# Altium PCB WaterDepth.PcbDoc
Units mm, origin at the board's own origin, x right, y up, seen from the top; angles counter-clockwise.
Board outline 26.42 x 32.13 mm, 2 copper layers (Top Layer, Bottom Layer); 43 components, 29 nets, 142 pads, 35 vias.
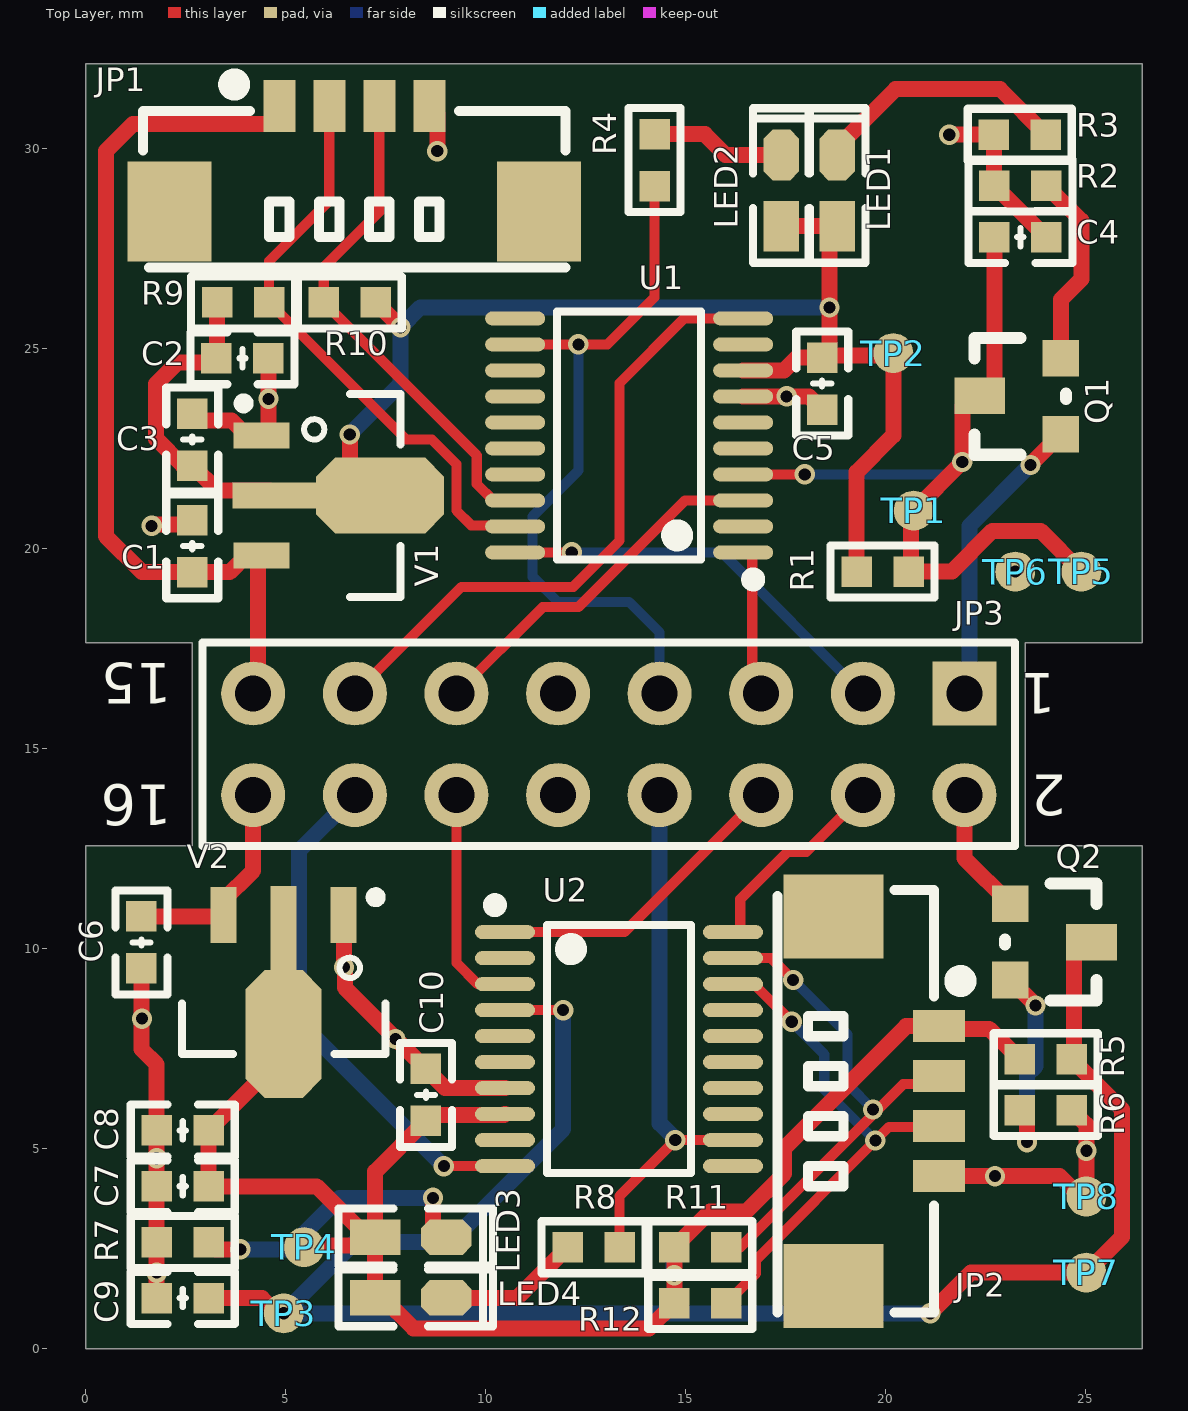
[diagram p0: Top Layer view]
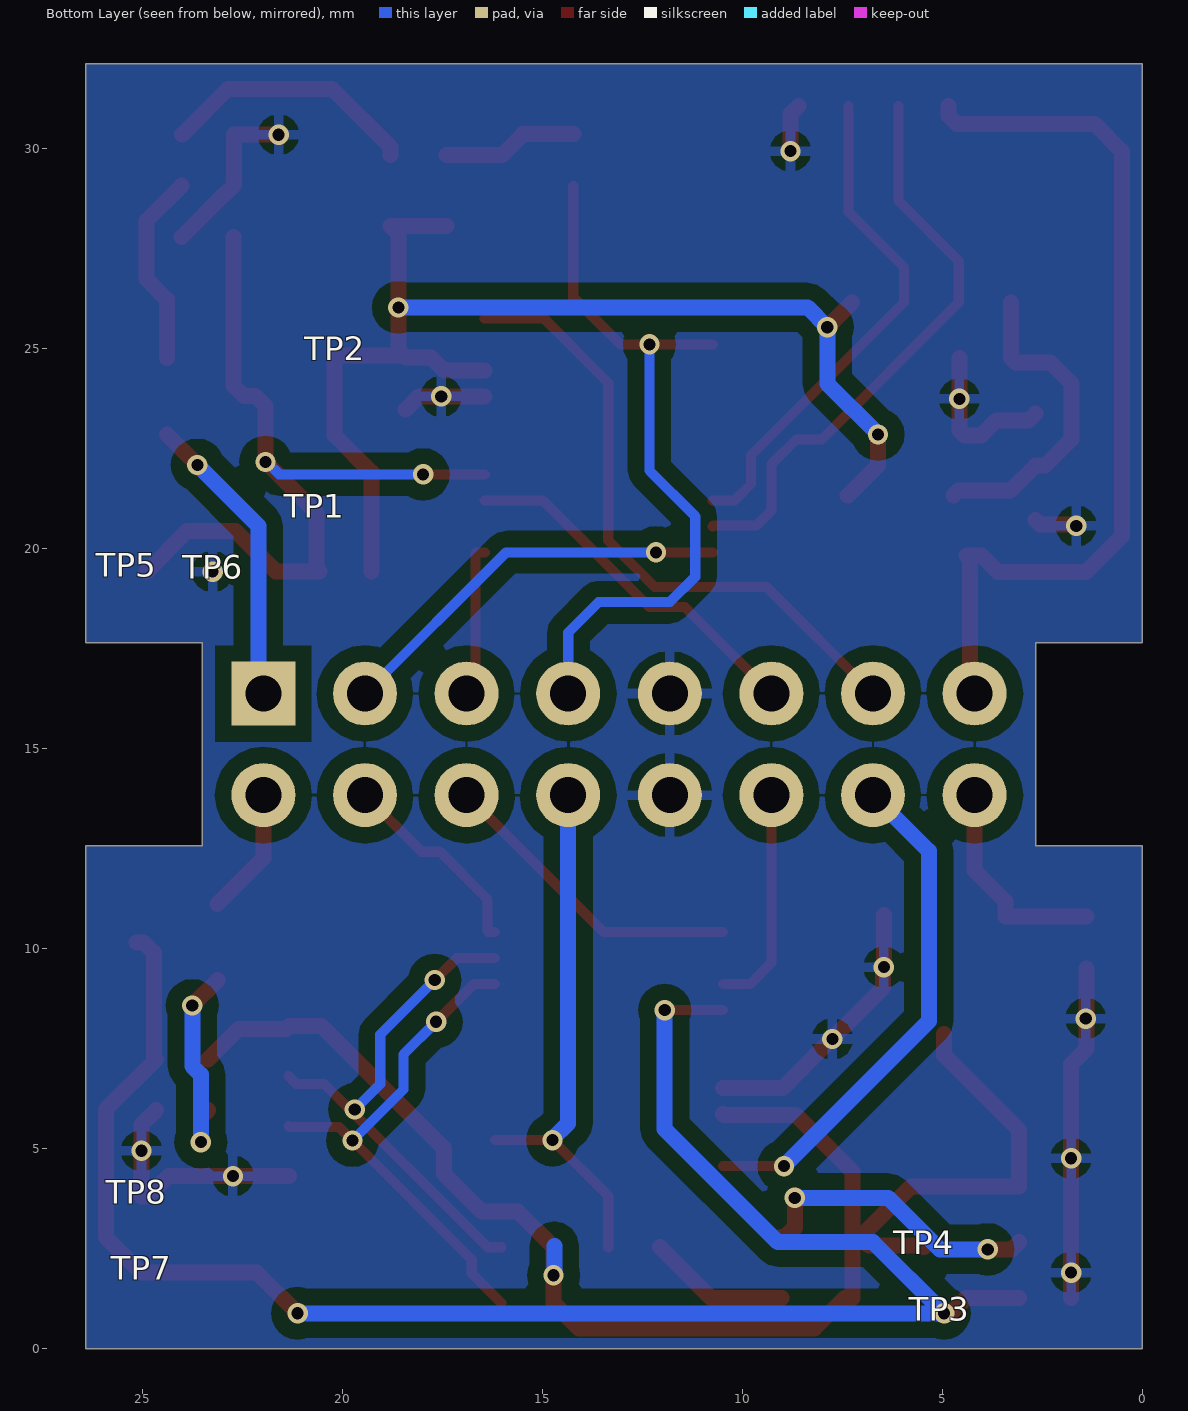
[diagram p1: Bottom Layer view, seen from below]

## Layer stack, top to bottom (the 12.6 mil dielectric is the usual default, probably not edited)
Top Solder: solder mask 0.0102, Solder Resist, Dk 3.5
Top Layer: signal copper 0.0356
Dielectric 1: dielectric 0.32, FR-4, Dk 4.8
Bottom Layer: signal copper 0.0356
Bottom Solder: solder mask 0.0102, Solder Resist, Dk 3.5

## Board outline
0,0 26.416,0 26.416,12.573 23.495,12.573 23.495,17.653 26.416,17.653 26.416,32.131 0,32.131 0,17.653 2.667,17.653 2.667,12.573 0,12.573

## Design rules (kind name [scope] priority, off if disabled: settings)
Clearance [All] p1: gap=0 ignorepadtopadclearanceinfootprint=FALSE
PolygonConnect [All] p1: connectstyle=Relief reliefconductorwidth=0.254 reliefentries=4 polygonreliefangle="90 Angle" airgapwidth=0.254
RoutingVias [All] p1: holewidth=0.711 width=1.27 viastyle="Through Hole" minholewidth=0.711 minwidth=1.27 maxholewidth=0.711 maxwidth=1.27
SilkToSilkClearance [All] p1: silktosilkclearance=0
SolderMaskExpansion [All] p1: expansion=0.102
Width [All] p1: maxlimit=1.5 minlimit=0.254 preferedwidth=0.4
29 further rules are at their usual default settings.

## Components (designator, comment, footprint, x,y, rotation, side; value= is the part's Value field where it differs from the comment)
C1 "104" "C 0603_L" 2.667,20.066 r270 top
C2 "104" "C 0603_L" 3.922,24.765 r180 top
C3 "104" "C 0603_L" 2.667,22.733 r270 top
C4 "104" "C 0603_L" 23.368,27.793 r180 top
C5 "104" "C 0603_L" 18.415,24.13 r90 top
C6 "104" "C 0603_L" 1.397,10.16 r90 top
C7 "104" "C 0603_L" 2.428,4.064 r0 top
C8 "104" "C 0603_L" 2.428,5.461 r0 top
C9 "104" "C 0603_L" 2.428,1.27 r0 top
C10 "104" "C 0603_L" 8.509,6.35 r270 top
JP1 "HDR-1X4" "MX 1.25-LS-4P" 6.731,28.814 r0 top
JP2 "HDR-1X4" "MX 1.25-LS-4P" 19.075,6.179 r270 top
JP3 "Header 8X2" HDR2.54-LI-2x8P 13.081,15.113 r180 top
LED1 "红色" "LED 0603W" 18.796,28.956 r90 top
LED2 "红色" "LED 0603W" 17.399,28.956 r90 top
LED3 "红色" "LED 0603W" 8.128,2.787 r0 top
LED4 "红色" "LED 0603W" 8.128,1.27 r0 top
Q1 "NPN" SOT-23 23.495,23.749 r90 top
Q2 "NPN" SOT-23 24.003,10.236 r270 top
R1 "33K" "R 0603_L" 19.924,19.431 r180 top
R2 "3.3K" "R 0603_L" 23.368,29.083 r0 top
R3 "3.3K" "R 0603_L" 23.353,30.353 r0 top
R4 "3.3K" "R 0603_L" 14.224,29.718 r90 top
R5 "33K" "R 0603_L" 24.003,7.239 r180 top
R6 "3.3K" "R 0603_L" 24.003,5.969 r180 top
R7 "3.3K" "R 0603_L" 2.428,2.667 r0 top
R8 "3.3K" "R 0603_L" 12.7,2.54 r180 top
R9 "4.7K" "R 0603_L" 3.937,26.162 r180 top
R10 "4.7K" "R 0603_L" 6.604,26.162 r0 top
R11 "4.7K" "R 0603_L" 15.367,2.54 r180 top
R12 "4.7K" "R 0603_L" 15.367,1.143 r180 top
TP1 "TEST" "TEST 1" 20.701,20.955 r180 top
TP2 "TEST" "TEST 1" 20.193,24.892 r270 top
TP3 "TEST" "TEST 1" 4.953,0.889 r90 top
TP4 "TEST" "TEST 1" 5.461,2.54 r90 top
TP5 "TEST" "TEST 1" 24.892,19.431 r90 top
TP6 "TEST" "TEST 1" 23.241,19.431 r90 top
TP7 "TEST" "TEST 1" 25.019,1.905 r90 top
TP8 "TEST" "TEST 1" 25.019,3.81 r90 top
U1 "STM8L101F3P6" TSSOP-20 13.589,22.836 r90 top
U2 "STM8L101F3P6" TSSOP-20 13.335,7.493 r270 top
V1 "AMS1117-3V3" SOT89_N 6.35,21.336 r270 top
V2 "AMS1117-3V3" SOT89_N 4.953,8.89 r180 top

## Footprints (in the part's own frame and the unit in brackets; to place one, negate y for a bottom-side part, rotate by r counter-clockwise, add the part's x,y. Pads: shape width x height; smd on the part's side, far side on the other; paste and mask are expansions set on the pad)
"C 0603_L" [mil] "无极性贴片电容"
  rect 30x30 smd: 1(-25.59,0) 2(25.59,0)
  silkscreen extent -51,-26 51,26, body extent -31,-16 31,16, height 32
HDR2.54-LI-2x8P [mm] "双排排针，8x2脚"
  rect 1.6x1.6 hole 0.9: 1(-8.89,-1.27)
  round 1.6 hole 0.9: 2(-8.89,1.27) 3(-6.35,-1.27) 4(-6.35,1.27) 5(-3.81,-1.27) 6(-3.81,1.27) 7(-1.27,-1.27) 8(-1.27,1.27) 9(1.27,-1.27) 10(1.27,1.27) 11(3.81,-1.27) 12(3.81,1.27) 13(6.35,-1.27) 14(6.35,1.27) 15(8.89,-1.27) 16(8.89,1.27)
  silkscreen extent -10.16,-2.54 10.16,2.54, body extent -10.16,-2.54 10.16,2.54, height 8.5
"LED 0603W" [mil] "白色0603LED"
  rect 50x35 smd: 1(-35,0.26)
  oct 50x35 smd: 2(35,0.26)
  silkscreen extent -71,-28 81,28, body extent -31,-16 32,16, height 18
"MX 1.25-LS-4P" [mm] "长：9.75m，宽：3.7mm，高：4.7mm"
  rect 2.1x2.5 smd: 0(-4.632,-0.381) 0(4.604,-0.381)
  rect 0.8x1.3 smd: 1(-1.889,2.261) 2(-0.639,2.261) 3(0.611,2.261) 4(1.861,2.261)
  silkscreen extent -5.29,-1.78 5.27,2.99, body extent -5.07,-1.6 5.07,2.5, height 4.7
"R 0603_L" [mil] "1/10W贴片电阻"
  rect 30x30 smd: 1(-25.59,0) 2(25.59,0)
  silkscreen extent -51,-26 51,26, body extent -31,-16 32,16, height 16
SOT89_N [mm] "4.6x4.3x1.6mm(长宽高)"
  rect 0.65x1.4 smd: 1(-1.5,-1.952) 3(1.5,-1.952)
  oct 1.9x3.2 smd: 2(0,1.016)
  rect 0.65x2.1 smd: 2(0,-1.626)
  silkscreen extent -2.54,-2.52 2.54,1.52, body extent -2.3,-2.4 2.3,1.9, height 1.6
SOT-23 [mil]
  rect 36x36 smd: B(-35,-35) E(40,-35)
  rect 36x50 smd: C(3,45)
  silkscreen extent -55,-40 60,50, body extent -54,-48 60,62, height 47
"TEST 1" [mm] "测试点1mm"
  round 1 smd paste-1: 1(0,0)
TSSOP-20 [mm]
  oval 0.35x1.5 smd: 1(-2.925,-2.85) 2(-2.275,-2.85) 3(-1.625,-2.85) 4(-0.975,-2.85) 5(-0.325,-2.85) 6(0.325,-2.85) 7(0.975,-2.85) 8(1.625,-2.85) 9(2.275,-2.85) 10(2.925,-2.85) 11(2.925,2.85) 12(2.275,2.85) 13(1.625,2.85) 14(0.975,2.85) 15(0.325,2.85) 16(-0.325,2.85) 17(-0.975,2.85) 18(-1.625,2.85) 19(-2.275,2.85) 20(-2.925,2.85)
  silkscreen extent -3.75,-3.25 3.1,1.8

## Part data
C1 C2 C3 C4 C5 C6 C7 C8 C9 C10: library part C, "无极性贴片电容"
JP1 JP2: library part "Header 4", "4P接插件"
JP3: "8*2P接插件"
LED1 LED2 LED3 LED4: library part LED-SMD, "贴片LED"
Q1 Q2: "NPN三极管"
R1 R2 R3 R4 R5 R6 R7 R8 R9 R10 R11 R12: library part R, "贴片电阻"
TP1 TP2 TP3 TP4 TP5 TP6 TP7 TP8: "测试点"
U1 U2: "MCU", Package=TSSOP-20, SuppliersPartNumber=C30044
V1 V2: library part AMS1117, "三端稳压芯片"

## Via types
v1: diameter 0.508, hole 0.305, Top Layer to Bottom Layer, tented both sides, 35 vias

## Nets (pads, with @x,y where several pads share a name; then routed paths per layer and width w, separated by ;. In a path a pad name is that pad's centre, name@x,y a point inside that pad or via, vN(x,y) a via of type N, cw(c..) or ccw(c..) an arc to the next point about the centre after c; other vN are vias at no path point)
3V3: C2.2 C3.2 C5.2 LED1.1 LED2.1 R1.2 R9.2 R10.2 TP2.1 U1.8 V1.2 | length 39.4
  Top Layer w0.4: R9.2 3.28,26.155 3.28,24.773 C2.2 3.16,24.653 2.291,24.653 1.763,24.125 1.763,22.748 2.428,22.083 C3.2 3.289,21.461 4.599,21.461 V1.2@4.724,21.336 ; v1(6.604,22.86) 6.604,22.086 7.354,21.336 V1.2@7.366,21.336 ; R10.2 v1(7.874,25.542) ; U1.8 17.461,24.461 17.78,24.78 C5.2 C5.2@18.471,24.836 ; LED2.1 LED1.1 18.596,27.874 v1(18.596,26.035) 18.596,24.961 C5.2@18.471,24.836 ; R1.2 19.274,21.917 20.193,22.836 20.193,24.78 20.137,24.836 C5.2@18.471,24.836
  Bottom Layer w0.4: v1(6.604,22.86) 7.874,24.13 v1(7.874,25.542) 8.367,26.035 v1(18.596,26.035)
3V3_B: C7.2 C8.2 C10.2 JP2.1 LED3.1 LED4.1 R5.2 R11.2 R12.2 TP4.1 U2.8 V2.2 | length 39.8
  Top Layer w0.4: V2.2@4.953,7.874 4.953,7.336 C8.2 C7.2 5.779,4.064 LED3.1@7.048,2.794 ; TP4.1 5.501,2.58 6.834,2.58 LED3.1@7.048,2.794 ; U2.8 10.46,5.843 8.652,5.843 C10.2 7.239,4.43 LED3.1 ; R5.2 22.591,8.001 21.403,8.001 JP2.1 20.514,8.068 17.461,5.015 17.461,4.38 16.51,3.429 15.606,3.429 R11.2 v1(14.717,1.842) R12.2 14.082,0.508 8.198,0.508 7.429,1.277 LED4.1 LED3.1 ; LED3.1@7.048,2.794 LED3.1
  Bottom Layer w0.4: 14.696,2.576 14.696,1.862 v1(14.717,1.842)
+5: C1.2 JP1.1 JP3.15 V1.3 | length 22.5
  Top Layer w0.4: JP3.15 4.31,16.502 4.31,19.748 V1.3 4.023,19.836 3.603,19.416 C1.2 1.412,19.416 0.508,20.32 0.508,29.943 1.19,30.625 4.642,30.625 4.842,30.825 JP1.1
+5_B: C6.2 JP3.16 V2.3 | length 5.4
  Top Layer w0.4: C6.2 3.421,10.81 3.421,11.185 4.191,11.955 JP3.16
Ctrl: JP3.1 Q1.B | length 7.5
  Top Layer w0.4: v1(23.622,22.098) Q1.B
  Bottom Layer w0.4: JP3.1 22.098,16.51 22.098,20.574 v1(23.622,22.098)
Ctrl_B: JP3.2 Q2.B | length 3.2
  Top Layer w0.4: JP3.2 21.971,12.268 Q2.B
GND: C1.1 C2.1 C3.1 C4.1 C5.1 C6.1 C7.1 C8.1 C9.1 C10.1 JP1.4 JP2.4 JP3.9 JP3.10 R2.1 R3.1 R6.1 R7.1 TP6.1 TP8.1 U1.7 U2.7 V1.1 V2.1 | length 34
  Top Layer w0.4: C6.1 1.397,7.493 1.778,7.112 C8.1 C7.1 R7.1 C9.1 ; v1@1.686,20.609 2.56,20.609 C1.1 ; C3.1 2.839,23.211 3.648,23.211 4.023,22.836 V1.1 4.447,22.836 4.572,22.961 v1(4.572,23.749) C2.1 ; V2.1 6.46,10.836 v1(6.46,9.542) 6.48,9.522 6.48,9.029 C10.1 8.991,6.518 U2.7 ; JP1.4 8.792,30.875 v1(8.792,29.943) ; U1.7 v1(17.526,23.811) 18.084,23.811 C5.1 ; JP2.4 24.349,4.318 24.857,3.81 TP8.1 25.019,5.603 R6.1 ; v1(21.59,30.353) R3.1 22.71,30.346 22.71,29.09 R2.1 22.899,28.902 22.909,28.902 C4.1
  other v1: 1.778,1.905 22.733,4.318 1.778,4.763 25.019,4.953 7.747,7.747 1.412,8.255 23.241,19.431 1.651,20.574
KEY: JP3.13 U1.10 | length 15.9
  Top Layer w0.254: JP3.13 9.398,19.05 12.192,19.05 13.35,20.208 13.35,24.145 14.966,25.761 U1.10
KEY_B: JP3.14 U2.10 | length 12.9
  Top Layer w0.254: v1(8.958,4.568) U2.10
  Bottom Layer w0.4: JP3.14 5.334,12.446 5.334,8.191 v1(8.958,4.568)
LED: JP3.7 R4.1 U1.12 | length 18.3
  Top Layer w0.254: U1.12 v1(12.319,25.111) 13.046,25.111 14.224,26.289 R4.1
  Bottom Layer w0.254: v1(12.319,25.111) 12.319,21.956 11.176,20.813 11.176,19.304 11.811,18.669 13.589,18.669 14.351,17.907 JP3.7
LED_B: JP3.8 R8.1 U2.12 | length 13.5
  Top Layer w0.254: R8.1 13.35,3.825 v1(14.743,5.218) U2.12
  Bottom Layer w0.4: JP3.8 14.351,5.639 14.743,5.247 v1(14.743,5.218)
NetC4_2: C4.2 Q1.C R1.1 TP1.1 TP5.1 U1.4 | length 20.2
  Top Layer w0.254: U1.4 v1(17.978,21.861)
  Top Layer w0.4: C4.2 22.718,24.082 22.461,23.825 Q1.C 22.174,23.825 21.917,23.568 v1(21.917,22.171) TP1.1 20.637,20.892 20.637,19.494 R1.1 21.654,19.431 22.67,20.447 23.876,20.447 TP5.1
  Bottom Layer w0.254: v1(17.978,21.861) 21.578,21.861 21.888,22.171 v1(21.917,22.171)
NetC9_2: C9.2 Q2.C R5.1 TP3.1 TP7.1 U2.4 | length 45.3
  Top Layer w0.254: U2.4 v1(11.938,8.468)
  Top Layer w0.4: C9.2 4.41,1.27 4.791,0.889 v1(4.953,0.889) ; v1(21.115,0.889) 22.131,1.905 TP7.1 25.908,2.794 25.908,5.984 R5.1 24.711,7.297 24.711,9.903 24.968,10.16 Q2.C
  Bottom Layer w0.4: v1(11.938,8.468) 11.938,5.494 9.111,2.667 6.731,2.667 v1(4.953,0.889) v1(21.115,0.889)
NetLED1_2: LED1.2 R3.2 | length 6.5
  Top Layer w0.4: LED1.2 18.789,30.036 20.25,31.496 22.86,31.496 R3.2
NetLED2_2: LED2.2 R4.2 | length 3.4
  Top Layer w0.4: R4.2 15.479,30.368 16.002,29.845 LED2.2
NetLED3_2: LED3.2 R7.2 | length 7.4
  Top Layer w0.4: R7.2 3.259,2.486 v1(3.864,2.486) ; v1(8.687,3.775) 8.687,3.039 8.932,2.794 LED3.2
  Bottom Layer w0.4: v1(3.864,2.486) 5.061,2.486 6.35,3.775 v1(8.687,3.775)
NetLED4_2: LED4.2 R8.2 | length 3.6
  Top Layer w0.4: LED4.2 10.786,1.277 R8.2
NetQ1_E: Q1.E R2.2 | length 4.9
  Top Layer w0.4: R2.2 24.892,28.209 24.892,26.741 24.384,26.233 Q1.E
NetQ2_E: Q2.E R6.2 | length 5.3
  Top Layer w0.4: Q2.E v1(23.749,8.585) ; R6.2 23.534,5.788 v1(23.534,5.168)
  Bottom Layer w0.4: v1(23.534,5.168) 23.534,6.853 23.749,7.068 v1(23.749,8.585)
SWIM: JP3.11 U1.3 | length 9.2
  Top Layer w0.254: JP3.11 11.43,18.542 12.319,18.542 14.988,21.211 U1.3
SWIM_B: JP3.12 U2.3 | length 5.6
  Top Layer w0.254: JP3.12 9.271,9.649 9.802,9.118 U2.3
WD_SCL: JP1.2 R9.1 U1.19 | length 14.7
  Top Layer w0.254: JP1.2 6.092,28.698 4.587,27.193 R9.1 8.016,22.733 8.653,22.733 9.271,22.115 9.271,20.955 9.64,20.586 10.714,20.586 U1.19
WD_SCL_B: JP2.2 R11.1 U2.19 | length 12.9
  Top Layer w0.254: R11.1 16.365,2.54 20.443,6.618 21.136,6.618 JP2.2 ; U2.19 17.141,9.768 v1(17.689,9.22)
  Bottom Layer w0.254: v1(17.689,9.22) 19.05,7.859 19.05,6.619 v1(19.685,5.984)
WD_SDA: JP1.3 R10.1 U1.18 | length 12.7
  Top Layer w0.254: JP1.3 7.342,28.428 5.954,27.04 R10.1 9.779,22.337 9.779,21.622 10.19,21.211 U1.18
WD_SDA_B: JP2.3 R12.1 U2.18 | length 13
  Top Layer w0.254: R12.1 16.764,1.89 16.764,2.227 v1(19.744,5.207) 20.086,5.549 21.317,5.549 JP2.3 ; U2.18 16.71,9.118 v1(17.653,8.175)
  Bottom Layer w0.254: v1(17.653,8.175) 18.467,7.361 18.467,6.483 v1(19.744,5.207)
WD_UART_RX: JP3.3 U1.20 | length 10.2
  Top Layer w0.254: U1.20 v1(12.156,19.911)
  Bottom Layer w0.254: v1(12.156,19.911) 15.903,19.911 JP3.3
WD_UART_RX_B: JP3.4 U2.20 | length 5.1
  Top Layer w0.254: U2.20 16.342,10.418 16.367,10.443 16.367,11.243 17.552,12.428 18.016,12.428 JP3.4
WD_UART_TX: JP3.5 U1.1 | length 3.8
  Top Layer w0.254: U1.1 16.64,19.911 16.665,19.886 16.665,16.609 JP3.5
WD_UART_TX_B: JP3.6 U2.1 | length 7.8
  Top Layer w0.254: U2.1 13.466,10.418 JP3.6
pads on no net: JP1.0 JP2.0 U1.2 U1.5 U1.6 U1.9 U1.11 U1.13 U1.14 U1.15 U1.16 U1.17 U2.2 U2.5 U2.6 U2.9 U2.11 U2.13 U2.14 U2.15 U2.16 U2.17

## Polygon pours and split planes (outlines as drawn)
GND on Bottom Layer "Bottom Layer-GND" (solid, pour order 0): 0,32.131 26.416,32.131 26.416,17.653 23.495,17.653 23.495,12.573 26.416,12.573 26.416,0 0,0 0,12.573 2.667,12.573 2.667,17.653 0,17.653

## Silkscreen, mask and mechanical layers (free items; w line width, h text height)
Mechanical 1:
  lines w0.254: 0,0 0,12.573 2.667,12.573 2.667,17.653 0,17.653 0,32.131 26.416,32.131 26.416,31.75 26.416,31.496 26.416,30.988 26.416,30.48 26.416,17.653 23.495,17.653 23.495,12.573 26.416,12.573 26.416,0 26.035,0 25.4,0 1.016,0 0,0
